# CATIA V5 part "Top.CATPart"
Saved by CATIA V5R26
Part number: Part1.1
Bounding box of the stored display mesh (mm): x -50 to 50, y -25 to 25, z -20 to 0
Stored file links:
  D:\_Deepak\CATIA\CATIA V5-6R2016_Deepak\Resources\Part files\Partfiles\c12_catia_v5_6r2016_prt\c12_catia_v5-6r2016 figr_12-8\Top.CATPart
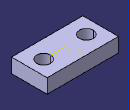
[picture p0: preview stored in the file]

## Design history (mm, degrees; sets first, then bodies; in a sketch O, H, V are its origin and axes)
Body1 (main body)
  Sketch1 on xy-plane, origin (0, 0, 0), H (1, 0, 0), V (0, 1, 0)
    line L1 (50, 25) -> (50, -25)
    line L2 (50, -25) -> (-50, -25)
    line L3 (-50, -25) -> (-50, 25)
    line L4 (-50, 25) -> (50, 25)
    circle A1 centre (-30, 0) radius 10
    point P5 (-30, 0)
    circle A2 centre (30, 0) radius 10
    length L2 = 100
    length L1 = 50
    radius A1 = 10
    distance P5 V = 30
    vertical: L1 V, L3 V
    horizontal: L2 H, L4 H
    equidistance: L1 L3 O, L2 L4 O
    coincidence: P5 H
    symmetry: A1 A2 V
  Pad1: profile Sketch1, direction (0, 0, -1), length 20
  Sketch2 on face of Pad1, origin (0, 0, 0), H (1, 0, 0), V (0, 1, 0)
